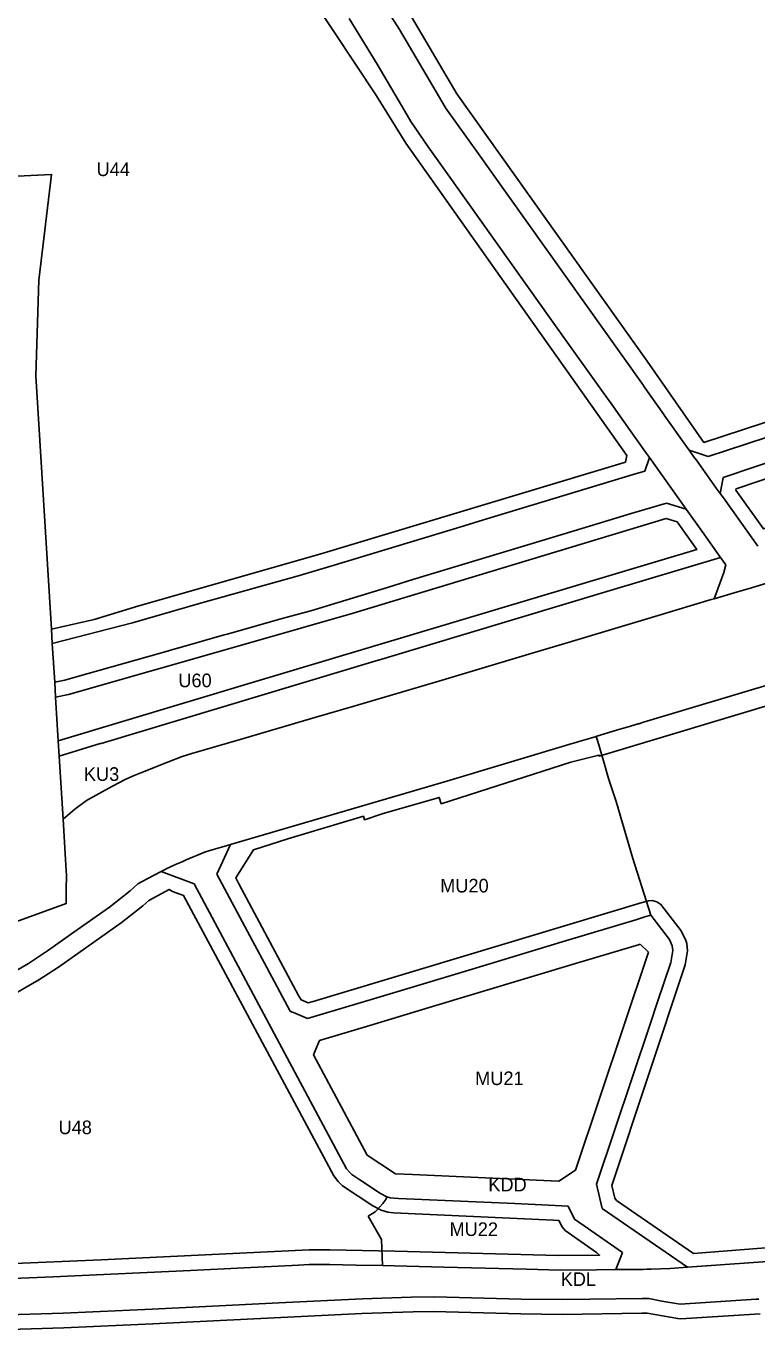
# Model space of a CAD drawing. Extents: x 7428103 to 7431580, y 5545880 to 5549002.
# Drawn here: x 7429340 to 7429639, y 5547123 to 5547655 of the extents above; entities that cross this region are included whole.
import ezdxf

# ---------------------------------------------------------------- set-up
doc = ezdxf.new("R2010")
doc.units = 0
for name, color, linetype in [('CZ_L_linie rozgraniczające tereny o różnym przeznaczeniu oraz różnych warunkach ich zabudowy i zagospodarowania', 7, 'Continuous'), ('CZ_L_maksymalne nieprzekraczalne linie zabudowy', 7, 'Continuous'), ('CZ_L_opisy_linie rozgraniczające tereny o różnym przeznaczeniu oraz różnych warunkach ich zabudowy i zagospodarowania', 7, 'Continuous'), ('CZYŻYNY - REJON ULICY GALICYJSKIEJ', 7, 'Continuous')]:
    doc.layers.add(name, color=color, linetype=linetype)

msp = doc.modelspace()

# ---------------------------------------------------------------- linework, layer by layer
at = {"layer": 'CZ_L_linie rozgraniczające tereny o różnym przeznaczeniu oraz różnych warunkach ich zabudowy i zagospodarowania'}
for p, q in [((7429483.58, 5547639.4), (7429472.15, 5547658.01)), ((7429489.36, 5547658.82), (7429492.67, 5547653.47)), ((7429492.67, 5547653.47), (7429507.7, 5547628.03)), ((7429483.6, 5547639.36), (7429483.58, 5547639.4)), ((7429494.91, 5547620.17), (7429483.6, 5547639.36)), ((7429507.7, 5547628.03), (7429511.37, 5547621.79)), ((7429511.37, 5547621.79), (7429511.41, 5547621.72)), ((7429511.41, 5547621.72), (7429511.49, 5547621.6)), ((7429511.49, 5547621.6), (7429524.96, 5547602.81)), ((7429497.33, 5547616.06), (7429494.91, 5547620.17)), ((7429504.38, 5547605.73), (7429497.33, 5547616.06)), ((7429512.54, 5547594.28), (7429504.38, 5547605.73)), ((7429524.96, 5547602.81), (7429536.6, 5547586.36)), ((7429557.76, 5547530.82), (7429512.54, 5547594.28)), ((7429536.6, 5547586.36), (7429536.61, 5547586.35)), ((7429536.61, 5547586.35), (7429592.23, 5547508.29)), ((7429574.41, 5547507.43), (7429557.76, 5547530.82)), ((7429578.22, 5547502.07), (7429574.41, 5547507.43)), ((7429592.23, 5547508.29), (7429592.33, 5547508.14)), ((7429592.33, 5547508.14), (7429600.53, 5547496.52)), ((7429578.24, 5547502.06), (7429578.22, 5547502.07)), ((7429578.34, 5547501.93), (7429578.24, 5547502.06)), ((7429578.36, 5547501.9), (7429578.34, 5547501.93)), ((7429588.43, 5547487.7), (7429578.36, 5547501.9)), ((7429600.53, 5547496.52), (7429600.73, 5547496.24)), ((7429600.73, 5547496.24), (7429600.74, 5547496.23)), ((7429600.74, 5547496.23), (7429609.85, 5547483.48)), ((7429618.66, 5547479.36), (7429651.63, 5547490.12)), ((7429593.47, 5547480.64), (7429588.43, 5547487.7)), ((7429609.85, 5547483.48), (7429610.99, 5547481.89)), ((7429594.71, 5547478.91), (7429592.82, 5547473.39)), ((7429594.71, 5547478.91), (7429593.47, 5547480.64)), ((7429609.72, 5547457.88), (7429594.71, 5547478.91)), ((7429612.76, 5547479.41), (7429610.99, 5547481.89)), ((7429610.99, 5547481.89), (7429618.66, 5547479.36)), ((7429613.91, 5547477.81), (7429612.76, 5547479.41)), ((7429620.06, 5547469.2), (7429613.91, 5547477.81)), ((7429656.35, 5547481.37), (7429624.8, 5547470.79)), ((7429589.45, 5547472.38), (7429527.04, 5547453.54)), ((7429592.82, 5547473.39), (7429589.45, 5547472.38)), ((7429621.98, 5547466.52), (7429620.06, 5547469.2)), ((7429623.62, 5547464.23), (7429621.98, 5547466.52)), ((7429624.15, 5547467.18), (7429623.62, 5547464.23)), ((7429624.8, 5547470.79), (7429624.15, 5547467.18)), ((7429623.62, 5547464.23), (7429624.88, 5547462.46)), ((7429624.88, 5547462.46), (7429638.93, 5547442.74)), ((7429587.3, 5547456.06), (7429563.98, 5547449.03)), ((7429601.63, 5547460.39), (7429587.3, 5547456.06)), ((7429609.72, 5547457.88), (7429601.63, 5547460.39)), ((7429616.24, 5547448.74), (7429609.72, 5547457.88)), ((7429519.08, 5547451.14), (7429464.66, 5547434.64)), ((7429527.04, 5547453.54), (7429519.08, 5547451.14)), ((7429552.24, 5547445.48), (7429498.1, 5547429.15)), ((7429552.25, 5547445.49), (7429552.24, 5547445.48)), ((7429563.98, 5547449.03), (7429552.25, 5547445.49)), ((7429623.76, 5547438.18), (7429616.24, 5547448.74)), ((7429464.66, 5547434.64), (7429451.97, 5547430.79)), ((7429623.76, 5547438.18), (7429577.28, 5547424.25)), ((7429625.94, 5547435.13), (7429623.76, 5547438.18)), ((7429625.09, 5547432.02), (7429625.94, 5547435.13)), ((7429451.97, 5547430.79), (7429411.5, 5547419.5)), ((7429621.1, 5547421.34), (7429625.09, 5547432.02)), ((7429488.25, 5547426.14), (7429470.84, 5547420.84)), ((7429577.28, 5547424.25), (7429484.1, 5547396.36)), ((7429498.1, 5547429.15), (7429488.25, 5547426.14)), ((7429630.68, 5547424.17), (7429625.16, 5547422.54)), ((7429634.96, 5547425.43), (7429630.68, 5547424.17)), ((7429644.37, 5547428.21), (7429634.96, 5547425.43)), ((7429411.5, 5547419.5), (7429383.73, 5547411.52)), ((7429470.84, 5547420.84), (7429456.51, 5547416.47)), ((7429598.24, 5547414.51), (7429619.88, 5547420.98)), ((7429619.88, 5547420.98), (7429621.1, 5547421.34)), ((7429625.16, 5547422.54), (7429621.1, 5547421.34)), ((7429447.9, 5547414.08), (7429443.89, 5547412.96)), ((7429456.51, 5547416.47), (7429447.9, 5547414.08)), ((7429561.57, 5547403.53), (7429598.24, 5547414.51)), ((7429383.73, 5547411.52), (7429351.04, 5547403.15)), ((7429443.89, 5547412.96), (7429422.39, 5547406.96)), ((7429421.21, 5547406.63), (7429402.22, 5547401.24)), ((7429422.39, 5547406.96), (7429421.21, 5547406.63)), ((7429545.47, 5547398.71), (7429561.57, 5547403.53)), ((7429390.24, 5547397.84), (7429360.36, 5547389.34)), ((7429396.54, 5547399.63), (7429390.24, 5547397.84)), ((7429402.07, 5547401.2), (7429396.54, 5547399.63)), ((7429402.22, 5547401.24), (7429402.07, 5547401.2)), ((7429508.82, 5547387.76), (7429545.47, 5547398.71)), ((7429484.07, 5547396.35), (7429370.93, 5547362.35)), ((7429484.1, 5547396.36), (7429484.07, 5547396.35)), ((7429356.21, 5547388.16), (7429352.02, 5547387.28)), ((7429360.36, 5547389.34), (7429356.21, 5547388.16)), ((7429473.74, 5547377.43), (7429508.82, 5547387.76)), ((7429648.15, 5547387.7), (7429592.29, 5547370.97)), ((7429458.12, 5547372.87), (7429473.74, 5547377.43)), ((7429427.76, 5547363.99), (7429458.12, 5547372.87)), ((7429592.29, 5547370.97), (7429590.35, 5547370.39)), ((7429582.69, 5547368.1), (7429573.26, 5547365.28)), ((7429585.64, 5547368.98), (7429582.69, 5547368.1)), ((7429588.7, 5547369.9), (7429585.64, 5547368.98)), ((7429589.94, 5547370.27), (7429588.7, 5547369.9)), ((7429590.35, 5547370.39), (7429589.94, 5547370.27)), ((7429370.59, 5547362.25), (7429353.87, 5547357.2)), ((7429370.93, 5547362.35), (7429370.59, 5547362.25)), ((7429407.98, 5547358.17), (7429427.76, 5547363.99)), ((7429512.07, 5547346.96), (7429563.21, 5547362.27)), ((7429563.21, 5547362.27), (7429565.27, 5547362.89)), ((7429565.27, 5547362.89), (7429565.48, 5547362.95)), ((7429565.48, 5547362.95), (7429570.23, 5547364.37)), ((7429570.23, 5547364.37), (7429572.99, 5547365.2)), ((7429573.26, 5547365.28), (7429572.99, 5547365.2)), ((7429572.99, 5547365.2), (7429573.63, 5547363.11)), ((7429573.63, 5547363.11), (7429575.91, 5547355.31)), ((7429387.13, 5547350.36), (7429398.43, 5547354.81)), ((7429398.43, 5547354.81), (7429403.97, 5547356.99)), ((7429403.97, 5547356.99), (7429407.98, 5547358.17)), ((7429575.91, 5547355.31), (7429577.96, 5547348.03)), ((7429384.5, 5547349.23), (7429387.13, 5547350.36)), ((7429365.06, 5547339.08), (7429375.34, 5547344.75)), ((7429375.34, 5547344.75), (7429375.58, 5547344.88)), ((7429375.58, 5547344.88), (7429381.05, 5547347.74)), ((7429381.05, 5547347.74), (7429384.5, 5547349.23)), ((7429423.76, 5547321.16), (7429511.98, 5547346.94)), ((7429511.98, 5547346.94), (7429512.02, 5547346.95)), ((7429511.98, 5547346.94), (7429511.98, 5547346.94)), ((7429512.02, 5547346.95), (7429512.04, 5547346.96)), ((7429512.04, 5547346.96), (7429512.06, 5547346.96)), ((7429512.06, 5547346.96), (7429512.07, 5547346.96)), ((7429577.96, 5547348.03), (7429581.1, 5547338.71)), ((7429360.25, 5547335.48), (7429365.06, 5547339.08)), ((7429355.48, 5547331.48), (7429360.25, 5547335.48)), ((7429581.1, 5547338.71), (7429588.01, 5547315.45)), ((7429355.45, 5547331.45), (7429355.48, 5547331.48)), ((7429412.9, 5547317.89), (7429405.71, 5547314.89)), ((7429413.13, 5547317.99), (7429412.9, 5547317.89)), ((7429416.23, 5547318.92), (7429413.13, 5547317.99)), ((7429420.12, 5547320.09), (7429416.23, 5547318.92)), ((7429418.18, 5547309.07), (7429423.76, 5547321.16)), ((7429420.13, 5547320.09), (7429420.12, 5547320.09)), ((7429421.06, 5547320.37), (7429420.13, 5547320.09)), ((7429423.76, 5547321.16), (7429421.06, 5547320.37)), ((7429356.86, 5547308.44), (7429356.46, 5547315)), ((7429401.34, 5547312.91), (7429397.25, 5547311.07)), ((7429404.02, 5547314.12), (7429401.34, 5547312.91)), ((7429405.71, 5547314.89), (7429404.02, 5547314.12)), ((7429588.01, 5547315.45), (7429595.34, 5547292.3)), ((7429385.97, 5547305.08), (7429389.74, 5547307.08)), ((7429389.74, 5547307.08), (7429395.51, 5547310.14)), ((7429396.3, 5547310.56), (7429395.51, 5547310.14)), ((7429395.51, 5547310.14), (7429408.95, 5547305.12)), ((7429396.79, 5547310.82), (7429396.3, 5547310.56)), ((7429397.25, 5547311.07), (7429396.79, 5547310.82)), ((7429432.77, 5547281.77), (7429418.18, 5547309.07)), ((7429374.43, 5547295.59), (7429382.85, 5547302.23)), ((7429382.85, 5547302.23), (7429385.97, 5547305.08)), ((7429408.95, 5547305.12), (7429471.13, 5547188.83)), ((7429359.86, 5547285.32), (7429374.43, 5547295.59)), ((7429593.29, 5547291.74), (7429589.12, 5547290.37)), ((7429595.34, 5547292.3), (7429593.29, 5547291.74)), ((7429602.84, 5547282.39), (7429595.34, 5547292.3)), ((7429589.12, 5547290.37), (7429559.17, 5547281.37)), ((7429349.08, 5547277.8), (7429359.86, 5547285.32)), ((7429438.54, 5547270.98), (7429432.77, 5547281.77)), ((7429559.17, 5547281.37), (7429529.57, 5547272.48)), ((7429564.51, 5547272.54), (7429590.68, 5547280.4)), ((7429590.68, 5547280.4), (7429590.87, 5547280.46)), ((7429590.87, 5547280.46), (7429590.92, 5547280.47)), ((7429590.92, 5547280.47), (7429591, 5547280.5)), ((7429591, 5547280.5), (7429594.3, 5547277.18)), ((7429604.01, 5547279.77), (7429602.84, 5547282.39)), ((7429341.29, 5547272.65), (7429349.08, 5547277.8)), ((7429594.3, 5547277.18), (7429564.48, 5547188.27)), ((7429603.44, 5547273), (7429604.24, 5547277.88)), ((7429604.24, 5547277.88), (7429604.01, 5547279.77)), ((7429327.56, 5547264.7), (7429341.29, 5547272.65)), ((7429448.11, 5547253.09), (7429438.54, 5547270.98)), ((7429504.89, 5547254.62), (7429564.51, 5547272.54)), ((7429529.57, 5547272.48), (7429513.86, 5547267.75)), ((7429598.07, 5547256.97), (7429603.44, 5547273)), ((7429513.86, 5547267.75), (7429498.48, 5547263.13)), ((7429498.48, 5547263.13), (7429483.5, 5547258.63)), ((7429483.5, 5547258.63), (7429455.23, 5547250.13)), ((7429480.64, 5547247.33), (7429504.89, 5547254.62)), ((7429595.02, 5547247.87), (7429598.07, 5547256.97)), ((7429448.13, 5547253.09), (7429448.11, 5547253.09)), ((7429448.17, 5547253.09), (7429448.13, 5547253.09)), ((7429448.6, 5547252.91), (7429448.17, 5547253.09)), ((7429448.87, 5547252.8), (7429448.6, 5547252.91)), ((7429449.47, 5547252.55), (7429448.87, 5547252.8)), ((7429455.23, 5547250.13), (7429449.47, 5547252.55)), ((7429460.06, 5547241.15), (7429480.64, 5547247.33)), ((7429573.11, 5547182.54), (7429595.02, 5547247.87)), ((7429458.6, 5547237.7), (7429460.06, 5547241.15)), ((7429457.6, 5547235.34), (7429458.6, 5547237.7)), ((7429479.51, 5547194.36), (7429457.6, 5547235.34)), ((7429491.04, 5547186.82), (7429479.51, 5547194.36)), ((7429471.13, 5547188.83), (7429472.26, 5547187.47)), ((7429472.26, 5547187.47), (7429473.22, 5547186.58)), ((7429473.22, 5547186.58), (7429476.54, 5547184.35)), ((7429498, 5547186.51), (7429491.04, 5547186.82)), ((7429557.55, 5547183.86), (7429498, 5547186.51)), ((7429564.48, 5547188.27), (7429557.75, 5547183.86)), ((7429476.54, 5547184.35), (7429485.01, 5547178.81)), ((7429557.74, 5547183.85), (7429557.55, 5547183.86)), ((7429557.75, 5547183.86), (7429557.74, 5547183.85)), ((7429575.38, 5547172.72), (7429573.11, 5547182.54)), ((7429485.96, 5547174.77), (7429484.67, 5547173.28)), ((7429485.01, 5547178.81), (7429487.5, 5547177.48)), ((7429487.09, 5547176.33), (7429485.96, 5547174.77)), ((7429487.5, 5547177.48), (7429487.09, 5547176.33)), ((7429487.5, 5547177.48), (7429487.59, 5547177.43)), ((7429487.59, 5547177.43), (7429488.85, 5547177.06)), ((7429488.85, 5547177.06), (7429490.6, 5547176.83)), ((7429490.6, 5547176.83), (7429492.28, 5547176.75)), ((7429492.28, 5547176.75), (7429492.31, 5547176.75)), ((7429492.31, 5547176.75), (7429501.82, 5547176.33)), ((7429501.82, 5547176.33), (7429501.84, 5547176.33)), ((7429501.84, 5547176.33), (7429539.76, 5547174.64)), ((7429539.76, 5547174.64), (7429553.53, 5547174.03)), ((7429553.53, 5547174.03), (7429558.94, 5547173.79)), ((7429482.75, 5547171.37), (7429479.93, 5547169.48)), ((7429479.93, 5547169.48), (7429485.42, 5547160.02)), ((7429484.67, 5547173.28), (7429482.75, 5547171.37)), ((7429558.94, 5547173.79), (7429561.6, 5547173.68)), ((7429561.6, 5547173.68), (7429564.12, 5547168.36)), ((7429610.2, 5547148.7), (7429575.38, 5547172.72)), ((7429564.12, 5547168.36), (7429569.83, 5547164.38)), ((7429569.83, 5547164.38), (7429572.52, 5547162.51)), ((7429485.42, 5547160.02), (7429485.78, 5547149.39)), ((7429572.52, 5547162.51), (7429583.71, 5547154.78)), ((7429583.69, 5547154.73), (7429581.03, 5547147.72)), ((7429583.71, 5547154.78), (7429583.69, 5547154.73)), ((7429695.25, 5547154.73), (7429610.2, 5547148.7)), ((7429429.28, 5547148.44), (7429407.48, 5547147.39)), ((7429451.49, 5547149.59), (7429429.28, 5547148.44)), ((7429455.86, 5547149.82), (7429451.49, 5547149.59)), ((7429464.09, 5547149.87), (7429455.86, 5547149.82)), ((7429475.1, 5547149.62), (7429464.09, 5547149.87)), ((7429485.78, 5547149.39), (7429475.1, 5547149.62)), ((7429490.7, 5547149.28), (7429485.78, 5547149.39)), ((7429510.85, 5547148.69), (7429490.7, 5547149.28)), ((7429544.61, 5547147.87), (7429510.85, 5547148.69)), ((7429558.32, 5547147.54), (7429544.61, 5547147.87)), ((7429573.07, 5547147.67), (7429558.32, 5547147.54)), ((7429581.03, 5547147.72), (7429573.07, 5547147.67)), ((7429581.03, 5547147.72), (7429589.28, 5547147.76)), ((7429589.28, 5547147.76), (7429592.15, 5547147.85)), ((7429592.15, 5547147.85), (7429593.66, 5547147.9)), ((7429593.66, 5547147.9), (7429595.44, 5547147.95)), ((7429595.44, 5547147.95), (7429603.15, 5547148.2)), ((7429603.15, 5547148.2), (7429610.2, 5547148.7)), ((7429351.35, 5547144.79), (7429331.73, 5547144.02)), ((7429369.14, 5547145.58), (7429351.35, 5547144.79)), ((7429407.48, 5547147.39), (7429369.14, 5547145.58)), ((7429391.76, 5547131.59), (7429355.44, 5547129.96)), ((7429410.97, 5547132.54), (7429391.76, 5547131.59)), ((7429443.45, 5547134.14), (7429410.97, 5547132.54)), ((7429477.66, 5547135.87), (7429443.45, 5547134.14)), ((7429497.51, 5547136.54), (7429477.66, 5547135.87)), ((7429506.96, 5547136.67), (7429497.51, 5547136.54)), ((7429542.38, 5547135.69), (7429506.96, 5547136.67)), ((7429559.16, 5547135.5), (7429542.38, 5547135.69)), ((7429570.33, 5547135.7), (7429559.16, 5547135.5)), ((7429591.71, 5547136.02), (7429570.33, 5547135.7)), ((7429594.5, 5547135.91), (7429591.71, 5547136.02)), ((7429599.79, 5547134.91), (7429594.5, 5547135.91)), ((7429607.26, 5547133.66), (7429599.79, 5547134.91)), ((7429638.24, 5547135.65), (7429607.26, 5547133.66)), ((7429639.35, 5547135.73), (7429638.24, 5547135.65)), ((7429355.44, 5547129.96), (7429310.91, 5547128.6))]:
    msp.add_line(p, q, dxfattribs=at)
for points in [[(7429356.46, 5547315), (7429355.45, 5547331.45), (7429353.87, 5547357.2), (7429353.49, 5547363.35), (7429352.39, 5547381.24), (7429352.02, 5547387.28), (7429351.04, 5547403.15), (7429350.68, 5547408.98), (7429344.33, 5547512.3), (7429345.51, 5547551.35), (7429350.77, 5547594.37), (7429232.96, 5547588.73)], [(7429169.2, 5547233.58), (7429261.57, 5547262.53), (7429356.72, 5547297.08), (7429356.72, 5547302.84), (7429356.86, 5547308.44)]]:
    msp.add_lwpolyline(points, dxfattribs=at)
at = {"layer": 'CZ_L_maksymalne nieprzekraczalne linie zabudowy'}
for points in [[(7429350.68, 5547408.98), (7429368.07, 5547412.95), (7429386.29, 5547418.49), (7429460.25, 5547439.49), (7429584.94, 5547477.06), (7429585.5, 5547479.83), (7429495.31, 5547607.21), (7429483.29, 5547626.42), (7429422.21, 5547718.65), (7429357.55, 5547821.09), (7429348.01, 5547837.72), (7429327.54, 5547851.7), (7429222.85, 5547846.55)], [(7429432.98, 5547762.57), (7429443.33, 5547745.41), (7429497.66, 5547658.67), (7429516.16, 5547627.33), (7429593.82, 5547518.3), (7429616.89, 5547485.09), (7429649.28, 5547495.66), (7429697.79, 5547521.36), (7429709.74, 5547525.83), (7429768.93, 5547549.39), (7429774.37, 5547552.18), (7429874.72, 5547592.88)], [(7429712.49, 5547503.45), (7429694.08, 5547494.43), (7429658.71, 5547475.84), (7429630.07, 5547466.23), (7429629.97, 5547465.65), (7429641.26, 5547449.8), (7429757.88, 5547484.66), (7429771.7, 5547489.24), (7429905.93, 5547537.32), (7429926.05, 5547548.72)], [(7429353.49, 5547363.35), (7429430.84, 5547386.71), (7429614.04, 5547441.49), (7429606.01, 5547452.75), (7429601.61, 5547454.11), (7429473.79, 5547415.47), (7429431.12, 5547403.17), (7429357.66, 5547382.34), (7429352.39, 5547381.24)], [(7429650.23, 5547379.97), (7429574.15, 5547357.19), (7429574.08, 5547357.61), (7429562.7, 5547354.64), (7429509.75, 5547337.72), (7429508.96, 5547340.33), (7429485.68, 5547333.59), (7429478.46, 5547331.21), (7429478.03, 5547332.65), (7429447.22, 5547323.43), (7429433.09, 5547318.99), (7429425.96, 5547307.49), (7429427.11, 5547305.08), (7429451.44, 5547259.58), (7429452.58, 5547257.75), (7429455.4, 5547256.57), (7429457.52, 5547257.09), (7429591.7, 5547297.52), (7429594.29, 5547298.21), (7429595.87, 5547298.27), (7429597.77, 5547297.79), (7429599.4, 5547296.71), (7429607.69, 5547285.92), (7429609.61, 5547281.93), (7429609.92, 5547280.78), (7429610.24, 5547277.74), (7429609.36, 5547272.03), (7429579.38, 5547182.04), (7429580.59, 5547176.82), (7429581.24, 5547175.97), (7429612.64, 5547154.3)], [(7429332.53, 5547150.06), (7429370.96, 5547151.68), (7429455.81, 5547155.82), (7429464.23, 5547155.87), (7429490.83, 5547155.28), (7429557.63, 5547153.56), (7429574.39, 5547153.68), (7429573.15, 5547154.78), (7429560.35, 5547163.69), (7429559.05, 5547165.15), (7429557.79, 5547167.71), (7429555.52, 5547167.93), (7429490.32, 5547170.84), (7429487.92, 5547171.14), (7429485.18, 5547171.94), (7429481.89, 5547173.69), (7429469.44, 5547181.93), (7429467.67, 5547183.61), (7429465.86, 5547185.96), (7429404.62, 5547300.34), (7429400.12, 5547302.02), (7429398.7, 5547302.78), (7429390.47, 5547298.35), (7429387.97, 5547296.09), (7429379.14, 5547289.13), (7429353.51, 5547271.14), (7429345.53, 5547265.87), (7429330.95, 5547257.45)], [(7429612.64, 5547154.3), (7429692.42, 5547160.54)], [(7429639.87, 5547129.69), (7429607.51, 5547127.67), (7429606.27, 5547127.74), (7429593.84, 5547129.92), (7429591.66, 5547130.02), (7429559.09, 5547129.5), (7429542.24, 5547129.69), (7429506.61, 5547130.67), (7429498.34, 5547130.55), (7429477.31, 5547129.85), (7429392.03, 5547125.59), (7429355.68, 5547123.96), (7429311.09, 5547122.6)]]:
    msp.add_lwpolyline(points, dxfattribs=at)
at = {"layer": 'CZYŻYNY - REJON ULICY GALICYJSKIEJ'}
msp.add_line((7429356.86, 5547308.44), (7429356.46, 5547315), dxfattribs=at)
for points in [[(7429356.46, 5547315), (7429355.45, 5547331.45), (7429353.87, 5547357.2), (7429353.49, 5547363.35), (7429352.39, 5547381.24), (7429352.02, 5547387.28), (7429351.04, 5547403.15), (7429350.68, 5547408.98), (7429344.33, 5547512.3), (7429345.51, 5547551.35), (7429350.77, 5547594.37), (7429232.96, 5547588.73)], [(7429169.2, 5547233.58), (7429261.57, 5547262.53), (7429356.72, 5547297.08), (7429356.72, 5547302.84), (7429356.86, 5547308.44)]]:
    msp.add_lwpolyline(points, dxfattribs=at)

# ---------------------------------------------------------------- texts
at = {"layer": 'CZ_L_opisy_linie rozgraniczające tereny o różnym przeznaczeniu oraz różnych warunkach ich zabudowy i zagospodarowania'}
for s, p in [('U44', (7429369.09, 5547593.73)), ('U60', (7429402.47, 5547385.27)), ('KU3', (7429363.92, 5547347.07)), ('MU20', (7429509.32, 5547301.56)), ('MU21', (7429523.6, 5547222.99)), ('U48', (7429353.59, 5547202.98)), ('KDD', (7429528.97, 5547179.66)), ('MU22', (7429513.13, 5547161.45)), ('KDL', (7429558.5, 5547141.07))]:
    msp.add_text(s, height=5.549, dxfattribs=at).set_placement(p)

doc.saveas('drawing.dxf')
